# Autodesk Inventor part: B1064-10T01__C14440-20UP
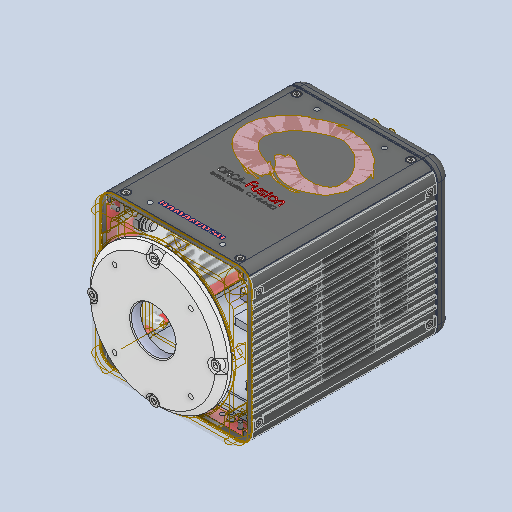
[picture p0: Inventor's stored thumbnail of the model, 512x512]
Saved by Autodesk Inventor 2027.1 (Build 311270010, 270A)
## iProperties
Created: 2019-05
Part Number: B1064-10T01__C14440-20UP
Material: Generic
Description: STEP AP214
Document SubType Name: Modeling
Designer: dunge
Density: 1 g/cm^3
Appearance: Default
Sending System: SolidWorks 2017
Preprocessor: SwSTEP 2.0
Title: B1064-10T01__C14440-20UP.STEP
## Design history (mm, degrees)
feature "20190510__C14440_ORCA-FUSION-1_2:1"
feature "20190510__C14440_ORCA-FUSION-2_3:1"
feature "20190510__C14440_ORCA-FUSION-3_4:1"
feature "20190510__C14440_ORCA-FUSION-4_5:1"
feature "20190510__C14440_ORCA-FUSION-5_6:1"
feature "20190510__C14440_ORCA-FUSION-6_7:1"
feature "20190510__C14440_ORCA-FUSION-7_8:1"
feature "20190510__C14440_ORCA-FUSION-8_9:1"
feature "20190510__C14440_ORCA-FUSION-9_10:1"
feature "20190510__C14440_ORCA-FUSION-10_11:1"
feature "20190510__C14440_ORCA-FUSION-11_12:1"
feature "20190510__C14440_ORCA-FUSION-12_13:1"
feature "20190510__C14440_ORCA-FUSION-13_14:1"
feature "20190510__C14440_ORCA-FUSION-14_15:1"
feature "20190510__C14440_ORCA-FUSION-15_16:1"
feature "20190510__C14440_ORCA-FUSION-16_17:1"
feature "20190510__C14440_ORCA-FUSION-17_18:1"
feature "20190510__C14440_ORCA-FUSION-18_19:1"
feature "20190510__C14440_ORCA-FUSION-19_20:1"
feature "20190510__C14440_ORCA-FUSION-20_21:1"
feature "20190510__C14440_ORCA-FUSION-21_22:1"
feature "20190510__C14440_ORCA-FUSION-22_23:1"
feature "20190510__C14440_ORCA-FUSION-23_24:1"
feature "20190510__C14440_ORCA-FUSION-24_25:1"
feature "20190510__C14440_ORCA-FUSION-25_26:1"
feature "20190510__C14440_ORCA-FUSION-26_27:1"
feature "20190510__C14440_ORCA-FUSION-27_28:1"
feature "20190510__C14440_ORCA-FUSION-28_29:1"
feature "20190510__C14440_ORCA-FUSION-29_30:1"
feature "20190510__C14440_ORCA-FUSION-30_31:1"
feature "20190510__C14440_ORCA-FUSION-31_32:1"
feature "20190510__C14440_ORCA-FUSION-32_33:1"
feature "20190510__C14440_ORCA-FUSION-33_34:1"
feature "20190510__C14440_ORCA-FUSION-34_35:1"
feature "20190510__C14440_ORCA-FUSION-35_36:1"
feature "20190510__C14440_ORCA-FUSION-36_37:1"
feature "20190510__C14440_ORCA-FUSION-37_38:1"
feature "20190510__C14440_ORCA-FUSION-38_39:1"
feature "20190510__C14440_ORCA-FUSION-39_40:1"
feature "20190510__C14440_ORCA-FUSION-40_41:1"
feature "20190510__C14440_ORCA-FUSION-41_42:1"
feature "20190510__C14440_ORCA-FUSION-42_43:1"
feature "20190510__C14440_ORCA-FUSION-43_44:1"
feature "20190510__C14440_ORCA-FUSION-44_45:1"
feature "20190510__C14440_ORCA-FUSION-45_46:1"
feature "20190510__C14440_ORCA-FUSION-46_47:1"
feature "20190510__C14440_ORCA-FUSION-47_48:1"
feature "20190510__C14440_ORCA-FUSION-48_49:1"
feature "20190510__C14440_ORCA-FUSION-49_50:1"
feature "20190510__C14440_ORCA-FUSION-50_51:1"
feature "20190510__C14440_ORCA-FUSION-51_52:1"
feature "20190510__C14440_ORCA-FUSION-52_53:1"
feature "20190510__C14440_ORCA-FUSION-53_54:1"
feature "20190510__C14440_ORCA-FUSION-54_55:1"
feature "20190510__C14440_ORCA-FUSION-55_56:1"
feature "20190510__C14440_ORCA-FUSION-56_57:1"
feature "20190510__C14440_ORCA-FUSION-57_58:1"
feature "20190510__C14440_ORCA-FUSION-58_59:1"
feature "20190510__C14440_ORCA-FUSION-59_60:1"
feature "20190510__C14440_ORCA-FUSION-60_61:1"
feature "20190510__C14440_ORCA-FUSION-61_62:1"
feature "20190510__C14440_ORCA-FUSION-62_63:1"
feature "20190510__C14440_ORCA-FUSION-63_64:1"
feature "20190510__C14440_ORCA-FUSION-64_65:1"
feature "20190510__C14440_ORCA-FUSION-65_66:1"
feature "20190510__C14440_ORCA-FUSION-66_67:1"
feature "20190510__C14440_ORCA-FUSION-67_68:1"
feature "20190510__C14440_ORCA-FUSION-68_69:1"
feature "20190510__C14440_ORCA-FUSION-69_70:1"
feature "20190510__C14440_ORCA-FUSION-70_71:1"
feature "20190510__C14440_ORCA-FUSION-71_72:1"
feature "20190510__C14440_ORCA-FUSION-72_73:1"
feature "20190510__C14440_ORCA-FUSION-73_74:1"
feature "20190510__C14440_ORCA-FUSION-74_75:1"
feature "20190510__C14440_ORCA-FUSION-75_76:1"
feature "20190510__C14440_ORCA-FUSION-76_77:1"
feature "20190510__C14440_ORCA-FUSION-77_78:1"
feature "20190510__C14440_ORCA-FUSION-78_79:1"
feature "20190510__C14440_ORCA-FUSION-79_80:1"
feature "20190510__C14440_ORCA-FUSION-80_81:1"
feature "20190510__C14440_ORCA-FUSION-81_82:1"
feature "20190510__C14440_ORCA-FUSION-82_83:1"
feature "20190510__C14440_ORCA-FUSION-83_84:1"
feature "20190510__C14440_ORCA-FUSION-84_85:1"
feature "20190510__C14440_ORCA-FUSION-85_86:1"
feature "20190510__C14440_ORCA-FUSION-86_87:1"
feature "20190510__C14440_ORCA-FUSION-87_88:1"
feature "20190510__C14440_ORCA-FUSION-88_89:1"
feature "20190510__C14440_ORCA-FUSION-89_90:1"
feature "20190510__C14440_ORCA-FUSION-90_91:1"
feature "20190510__C14440_ORCA-FUSION-91_92:1"
feature "20190510__C14440_ORCA-FUSION-92_93:1"
feature "20190510__C14440_ORCA-FUSION-93_94:1"
feature "20190510__C14440_ORCA-FUSION-94_95:1"
feature "20190510__C14440_ORCA-FUSION-95_96:1"
feature "20190510__C14440_ORCA-FUSION-96_97:1"
feature "20190510__C14440_ORCA-FUSION-97_98:1"
feature "20190510__C14440_ORCA-FUSION-98_99:1"
feature "20190510__C14440_ORCA-FUSION-99_100:1"
feature "20190510__C14440_ORCA-FUSION-100_101:1"
feature "20190510__C14440_ORCA-FUSION-101_102:1"
feature "20190510__C14440_ORCA-FUSION-102_103:1"
feature "20190510__C14440_ORCA-FUSION-103_104:1"
feature "20190510__C14440_ORCA-FUSION-104_105:1"
feature "20190510__C14440_ORCA-FUSION-105_106:1"
feature "20190510__C14440_ORCA-FUSION-106_107:1"
feature "20190510__C14440_ORCA-FUSION-107_108:1"
feature "20190510__C14440_ORCA-FUSION-108_109:1"
feature "20190510__C14440_ORCA-FUSION-109_110:1"
feature "20190510__C14440_ORCA-FUSION-110_111:1"
feature "20190510__C14440_ORCA-FUSION-111_112:1"
feature "20190510__C14440_ORCA-FUSION-112_113:1"
feature "20190510__C14440_ORCA-FUSION-113_114:1"
feature "20190510__C14440_ORCA-FUSION-114_115:1"
feature "20190510__C14440_ORCA-FUSION-115_116:1"
feature "20190510__C14440_ORCA-FUSION-116_117:1"
feature "20190510__C14440_ORCA-FUSION-117_118:1"
feature "20190510__C14440_ORCA-FUSION-118_119:1"
feature "20190510__C14440_ORCA-FUSION-119_120:1"
feature "20190510__C14440_ORCA-FUSION-120_121:1"
feature "20190510__C14440_ORCA-FUSION-121_122:1"
feature "20190510__C14440_ORCA-FUSION-122_123:1"
feature "20190510__C14440_ORCA-FUSION-123_124:1"
feature "20190510__C14440_ORCA-FUSION-124_125:1"
feature "20190510__C14440_ORCA-FUSION-125_126:1"
feature "20190510__C14440_ORCA-FUSION-126_127:1"
feature "20190510__C14440_ORCA-FUSION-127_128:1"
feature "20190510__C14440_ORCA-FUSION-128_129:1"
feature "20190510__C14440_ORCA-FUSION-129_130:1"
feature "20190510__C14440_ORCA-FUSION-130_131:1"
feature "20190510__C14440_ORCA-FUSION-131_132:1"
feature "20190510__C14440_ORCA-FUSION-132_133:1"
feature "20190510__C14440_ORCA-FUSION-133_134:1"
feature "20190510__C14440_ORCA-FUSION-134_135:1"
feature "20190510__C14440_ORCA-FUSION-135_136:1"
feature "20190510__C14440_ORCA-FUSION-136_137:1"
feature "20190510__C14440_ORCA-FUSION-137_138:1"
feature "20190510__C14440_ORCA-FUSION-138_139:1"
feature "20190510__C14440_ORCA-FUSION-139_140:1"
feature "20190510__C14440_ORCA-FUSION-140_141:1"
feature "20190510__C14440_ORCA-FUSION-141_142:1"
feature "20190510__C14440_ORCA-FUSION-142_143:1"
feature "20190510__C14440_ORCA-FUSION-143_144:1"
feature "20190510__C14440_ORCA-FUSION-144_145:1"
feature "20190510__C14440_ORCA-FUSION-145_146:1"
feature "20190510__C14440_ORCA-FUSION-146_147:1"
feature "20190510__C14440_ORCA-FUSION-147_148:1"
feature "20190510__C14440_ORCA-FUSION-148_149:1"
feature "20190510__C14440_ORCA-FUSION-149_150:1"
feature "20190510__C14440_ORCA-FUSION-150_151:1"
feature "20190510__C14440_ORCA-FUSION-151_152:1"
feature "20190510__C14440_ORCA-FUSION-152_153:1"
feature "20190510__C14440_ORCA-FUSION-153_154:1"
feature "20190510__C14440_ORCA-FUSION-154_155:1"
feature "20190510__C14440_ORCA-FUSION-155_156:1"
feature "20190510__C14440_ORCA-FUSION-156_157:1"
feature "Composite1"
workpoint "Work Point1"
  workaxis "Work Axis1"
body "Solid1"
body "Solid2"
body "Solid3"
body "Solid4"
body "Solid5"
body "Solid6"
body "Solid7"
body "Solid8"
body "Solid9"
body "Solid10"
body "Solid11"
body "Solid12"
body "Solid13"
body "Solid14"
body "Solid15"
body "Solid16"
body "Solid17"
body "Solid18"
body "Solid19"
body "Solid20"
body "Solid21"
body "Solid22"
body "Solid23"
body "Solid24"
body "Solid25"
body "Solid26"
body "Solid27"
body "Solid28"
body "Solid29"
body "Solid30"
body "Solid31"
body "Solid32"
body "Solid33"
body "Solid34"
body "Solid35"
body "Solid36"
body "Solid37"
body "Solid38"
body "Solid39"
body "Solid40"
body "Solid41"
body "Solid42"
body "Solid43"
body "Solid44"
body "Solid45"
body "Solid46"
body "Solid47"
body "Solid48"
body "Solid49"
body "Solid50"
body "Solid51"
body "Solid52"
body "Solid53"
body "Solid54"
body "Solid55"
body "Solid56"
body "Solid57"
body "Solid58"
body "Solid59"
body "Solid60"
body "Solid61"
body "Solid62"
body "Solid63"
body "Solid64"
body "Solid65"
body "Solid66"
body "Solid67"
body "Solid68"
body "Solid69"
body "Solid70"
body "Solid71"
body "Solid72"
body "Solid73"
body "Solid74"
body "Solid75"
body "Solid76"
body "Solid77"
body "Solid78"
body "Solid79"
body "Solid80"
body "Solid81"
body "Solid82"
body "Solid83"
body "Solid84"
body "Solid85"
body "Solid86"
body "Solid87"
body "Solid88"
body "Solid89"
body "Solid90"
body "Solid91"
body "Solid92"
body "Solid93"
body "Solid94"
body "Solid95"
body "Solid96"
body "Solid97"
body "Solid98"
body "Solid99"
body "Solid100"
body "Solid101"
body "Solid102"
body "Solid103"
body "Solid104"
body "Solid105"
body "Solid106"
body "Solid107"
body "Solid108"
body "Solid109"
body "Solid110"
body "Solid111"
body "Solid112"
body "Solid113"
body "Solid114"
body "Solid115"
body "Solid116"
body "Solid117"
body "Solid118"
body "Solid119"
body "Solid120"
body "Solid121"
body "Solid122"
body "Solid123"
body "Solid124"
body "Solid125"
body "Solid126"
body "Solid127"
body "Solid128"
body "Solid129"
body "Solid130"
body "Solid131"
body "Solid132"
body "Solid133"
body "Solid134"
body "Solid135"
body "Solid136"
body "Solid137"
body "Solid138"
body "Solid139"
body "Solid140"
body "Solid141"
body "Solid142"
body "Solid143"
body "Solid144"
body "Solid145"
body "Solid146"
body "Solid147"
body "Solid148"
body "Solid149"
body "Solid150"
body "Solid151"
body "Solid152"
body "Solid153"
body "Solid154"
body "Solid155"
body "Solid156"
body "Srf1"
